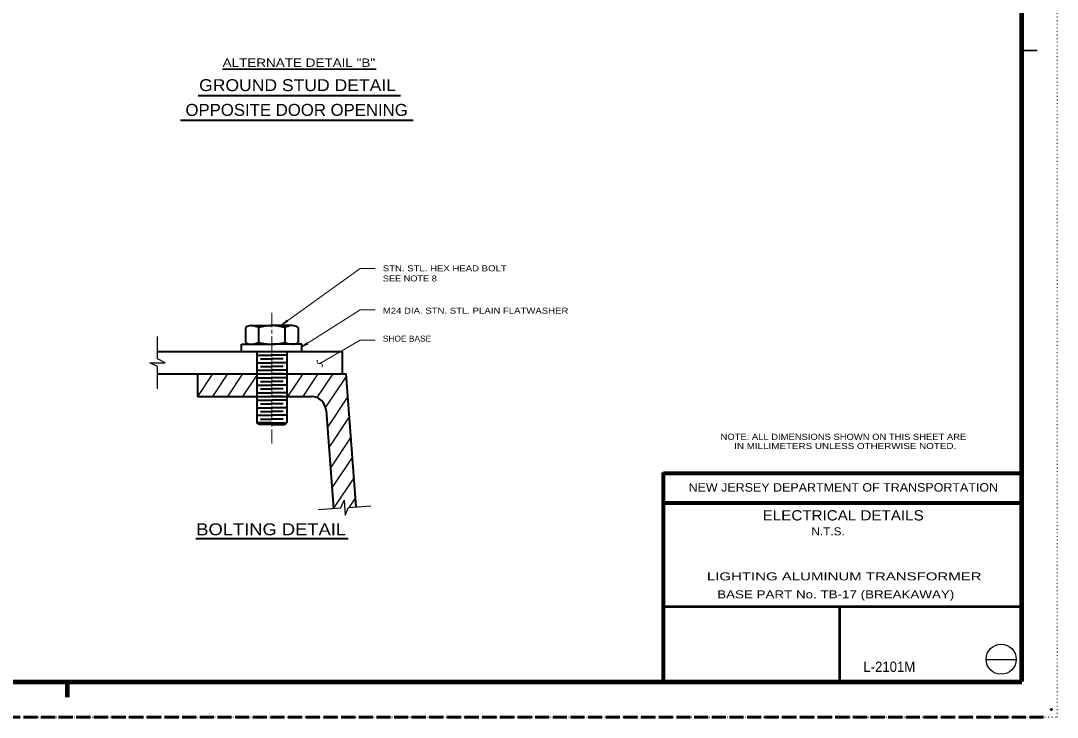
# Model space of a CAD drawing. Extents: x 312583 to 312854, y 144419 to 144597.
# Drawn here: x 312721.4 to 312853.5, y 144418.6 to 144507.4 of the extents above; entities that cross this region are included whole.
import ezdxf
from ezdxf.enums import TextEntityAlignment as Align

# ---------------------------------------------------------------- set-up
doc = ezdxf.new("R2010")
doc.units = 0
doc.header["$LTSCALE"] = 0.3
doc.header["$PDMODE"] = 32
doc.header["$PDSIZE"] = 0.15
for name, pattern in [('DOTTED', [1.5, 0.3, -1.2]), ('LONG_DASH_SHORT_DASH', [9.9, 6, -1.2, 1.5, -1.2]), ('LONG_DASHED', [7.5, 6, -1.5])]:
    doc.linetypes.add(name, pattern=pattern)
for name, color, linetype, lineweight in [('1', 7, 'Continuous', 40), ('2', 7, 'Continuous', 13), ('62', 7, 'DOTTED', 13), ('63', 7, 'LONG_DASHED', 60)]:
    doc.layers.add(name, color=color, linetype=linetype, lineweight=lineweight)

msp = doc.modelspace()

# ---------------------------------------------------------------- linework, layer by layer
at = {"layer": '1', "lineweight": 158}
for p, q in [((312849, 144423.1446), (312849, 144585.0846)), ((312616.5, 144423.0846), (312849, 144423.0846)), ((312727.35, 144421.1646), (312727.35, 144423.0846))]:
    msp.add_line(p, q, dxfattribs=at)
at = {"layer": '1', "lineweight": 35}
msp.add_line((312849, 144503.6216), (312850.932, 144503.6216), dxfattribs=at)
at = {"layer": '1', "linetype": 'LONG_DASH_SHORT_DASH', "lineweight": 13}
msp.add_line((312753.3623, 144453.4887), (312753.3623, 144470.3554), dxfattribs=at)
at = {"layer": '1'}
for p, q in [((312750.012, 144468.2931), (312750.012, 144466.3841)), ((312750.748, 144468.5384), (312753.3623, 144468.5384)), ((312751.691, 144468.2931), (312751.691, 144466.3841)), ((312755.9843, 144468.5384), (312753.3623, 144468.5384)), ((312755.0413, 144468.2931), (312755.0413, 144466.3841)), ((312756.7203, 144468.2931), (312756.7203, 144466.3841)), ((312749.529, 144465.2417), (312749.529, 144466.1464)), ((312749.529, 144466.1464), (312753.3623, 144466.1464)), ((312751.4456, 144465.2417), (312751.4456, 144456.1337)), ((312757.1956, 144466.1464), (312753.3623, 144466.1464)), ((312755.279, 144465.2417), (312755.279, 144456.1337)), ((312757.1956, 144465.2417), (312757.1956, 144466.1464)), ((312751.4456, 144464.7587), (312753.3623, 144464.7587)), ((312751.4456, 144463.8004), (312753.3623, 144463.8004)), ((312751.9286, 144464.2834), (312753.3623, 144464.2834)), ((312755.279, 144464.7587), (312753.3623, 144464.7587)), ((312754.8036, 144464.2834), (312753.3623, 144464.2834)), ((312755.279, 144463.8004), (312753.3623, 144463.8004)), ((312751.4456, 144462.8421), (312753.3623, 144462.8421)), ((312751.9286, 144463.3251), (312753.3623, 144463.3251)), ((312751.9286, 144462.3667), (312753.3623, 144462.3667)), ((312754.8036, 144463.3251), (312753.3623, 144463.3251)), ((312755.279, 144462.8421), (312753.3623, 144462.8421)), ((312754.8036, 144462.3667), (312753.3623, 144462.3667)), ((312751.4456, 144461.8837), (312753.3623, 144461.8837)), ((312751.9286, 144461.4084), (312753.3623, 144461.4084)), ((312755.279, 144461.8837), (312753.3623, 144461.8837)), ((312754.8036, 144461.4084), (312753.3623, 144461.4084)), ((312751.4456, 144460.9254), (312753.3623, 144460.9254)), ((312751.4456, 144459.9671), (312753.3623, 144459.9671)), ((312751.9286, 144460.4501), (312753.3623, 144460.4501)), ((312755.279, 144460.9254), (312753.3623, 144460.9254)), ((312754.8036, 144460.4501), (312753.3623, 144460.4501)), ((312755.279, 144459.9671), (312753.3623, 144459.9671)), ((312751.4456, 144459.0087), (312753.3623, 144459.0087)), ((312751.9286, 144459.4917), (312753.3623, 144459.4917)), ((312751.9286, 144458.5334), (312753.3623, 144458.5334)), ((312754.8036, 144459.4917), (312753.3623, 144459.4917)), ((312755.279, 144459.0087), (312753.3623, 144459.0087)), ((312754.8036, 144458.5334), (312753.3623, 144458.5334)), ((312751.4456, 144458.0504), (312753.3623, 144458.0504)), ((312751.4456, 144457.0921), (312753.3623, 144457.0921)), ((312751.9286, 144457.5751), (312753.3623, 144457.5751)), ((312755.279, 144458.0504), (312753.3623, 144458.0504)), ((312754.8036, 144457.5751), (312753.3623, 144457.5751)), ((312755.279, 144457.0921), (312753.3623, 144457.0921)), ((312753.3623, 144456.1337), (312751.4456, 144456.1337)), ((312751.7906, 144455.8961), (312751.4456, 144456.1337)), ((312753.3623, 144455.8961), (312751.7906, 144455.8961)), ((312751.9286, 144456.6167), (312753.3623, 144456.6167)), ((312754.8036, 144456.6167), (312753.3623, 144456.6167)), ((312753.3623, 144456.1337), (312755.279, 144456.1337)), ((312753.3623, 144455.8961), (312754.934, 144455.8961)), ((312754.934, 144455.8961), (312755.279, 144456.1337))]:
    msp.add_line(p, q, dxfattribs=at)
at = {"layer": '1', "lineweight": 80}
for p, q in [((312803.31, 144423.1446), (312803.31, 144449.8146)), ((312803.31, 144449.7246), (312849, 144449.7246)), ((312803.31, 144445.9146), (312849, 144445.9146))]:
    msp.add_line(p, q, dxfattribs=at)
at = {"layer": '1', "lineweight": 53}
for p, q in [((312849, 144432.6666), (312803.115, 144432.6666)), ((312825.7546, 144432.6666), (312825.7546, 144423.1446))]:
    msp.add_line(p, q, dxfattribs=at)
at = {"layer": '1', "lineweight": 25}
msp.add_line((312844.4384, 144425.966), (312848.2794, 144425.966), dxfattribs=at)
msp.add_circle((312846.3494, 144425.9805), 1.9159, dxfattribs=at)
at = {"layer": '1'}
for centre, radius, start, end in [((312750.7843, 144467.148), 1.3833, 91.66257, 124.1297), ((312750.1163, 144464.6567), 3.9611, 66.63635, 78.22986), ((312753.5376, 144461.3881), 7.1486, 91.405, 105.00202), ((312753.187, 144461.3881), 7.1486, 74.99798, 88.595), ((312756.6083, 144464.6567), 3.9611, 101.77014, 113.36365), ((312755.9403, 144467.148), 1.3833, 55.8703, 88.33743), ((312750.7843, 144467.5291), 1.3833, 235.8703, 268.33743), ((312750.1163, 144470.0204), 3.9611, 281.77014, 293.36365), ((312753.5376, 144473.2891), 7.1486, 254.99798, 268.595), ((312753.187, 144473.2891), 7.1486, 271.405, 285.00202), ((312756.6083, 144470.0204), 3.9611, 246.63635, 258.22986), ((312755.9403, 144467.5291), 1.3833, 271.66257, 304.1297)]:
    msp.add_arc(centre, radius, start, end, dxfattribs=at)
msp.add_point((312852.75, 144419.5846), dxfattribs=at)
at = {"layer": '2', "lineweight": 35}
msp.add_line((312747.078, 144501.2392), (312766.6956, 144501.2392), dxfattribs=at)
at = {"layer": '2', "lineweight": 40}
for p, q in [((312743.9953, 144497.8668), (312769.7783, 144497.8668)), ((312741.7532, 144494.7191), (312771.3897, 144494.7191)), ((312743.894, 144462.3667), (312743.894, 144459.4917)), ((312743.894, 144459.4917), (312758.384, 144459.4917)), ((312760.293, 144457.7131), (312761.2283, 144445.2011)), ((312743.7051, 144441.3688), (312763.1125, 144441.3688))]:
    msp.add_line(p, q, dxfattribs=at)
at = {"layer": '2'}
for p, q in [((312754.6503, 144468.6304), (312764.6476, 144475.7911)), ((312764.6476, 144475.7911), (312766.5643, 144475.7911)), ((312757.2186, 144465.8014), (312764.6476, 144470.5241)), ((312764.6476, 144470.5241), (312766.5643, 144470.5241)), ((312754.6503, 144468.6304), (312755.2866, 144469.2207)), ((312754.6503, 144468.6304), (312755.417, 144469.0521)), ((312755.2866, 144469.2207), (312755.1256, 144468.9754)), ((312755.417, 144469.0521), (312755.1256, 144468.9754)), ((312757.2186, 144465.8014), (312757.8933, 144466.3534)), ((312757.8933, 144466.3534), (312757.717, 144466.1157)), ((312759.488, 144463.6854), (312764.6476, 144466.6907)), ((312764.6476, 144466.6907), (312766.5643, 144466.6907)), ((312757.2186, 144465.8014), (312758.0083, 144466.1694)), ((312758.0083, 144466.1694), (312757.717, 144466.1157))]:
    msp.add_line(p, q, dxfattribs=at)
at = {"layer": '2', "lineweight": 25}
for p, q in [((312745.8106, 144462.3667), (312743.894, 144459.4917)), ((312747.7273, 144462.3667), (312745.8106, 144459.4917)), ((312749.644, 144462.3667), (312747.7273, 144459.4917)), ((312757.3106, 144462.3667), (312755.394, 144459.4917)), ((312759.2273, 144462.3667), (312757.3106, 144459.4917)), ((312761.144, 144462.3667), (312759.1276, 144459.3384)), ((312751.4456, 144462.1904), (312749.644, 144459.4917)), ((312762.8536, 144462.0524), (312760.224, 144458.1117)), ((312763.0453, 144459.4687), (312760.454, 144455.5817)), ((312763.2446, 144456.8851), (312760.6456, 144452.9981)), ((312763.4363, 144454.3014), (312760.845, 144450.4067)), ((312763.628, 144451.7101), (312761.0366, 144447.8231)), ((312763.8196, 144449.1264), (312761.2283, 144445.2394)), ((312764.0113, 144446.5427), (312763.2216, 144445.3544))]:
    msp.add_line(p, q, dxfattribs=at)
for points in [[(312738.8033, 144460.4501), (312738.8033, 144463.3174), (312737.845, 144463.8004), (312739.7616, 144463.8004), (312738.8033, 144464.2757), (312738.8033, 144467.1584)], [(312759.3193, 144445.0631), (312762.179, 144445.2701), (312762.593, 144446.2667), (312762.731, 144444.3577), (312763.1373, 144445.3467), (312766.0046, 144445.5614)]]:
    msp.add_lwpolyline(points, dxfattribs=at)
at = {"layer": '2', "lineweight": 40}
for points in [[(312738.8033, 144465.2417), (312762.3553, 144465.2417), (312762.3553, 144462.3667)], [(312738.8033, 144462.3667), (312762.8306, 144462.3667), (312764.0956, 144445.4157)]]:
    msp.add_lwpolyline(points, dxfattribs=at)
at = {"layer": '2'}
for centre, start, end in [((312759.4083, 144463.9456), 136.06269, 286.06269), ((312759.5573, 144463.4278), 316.06269, 106.06269)]:
    msp.add_arc(centre, 0.2694, start, end, dxfattribs=at)
at = {"layer": '2', "lineweight": 40}
msp.add_arc((312758.383, 144457.5712), 1.9167, 4.26806, 90, dxfattribs=at)
at = {"layer": '62'}
msp.add_lwpolyline([(312601.2, 144418.5846), (312853.5, 144418.5846), (312853.5, 144596.7846)], dxfattribs=at)
at = {"layer": '63'}
msp.add_line((312851.75, 144418.5846), (312583.526, 144418.5846), dxfattribs=at)

# ---------------------------------------------------------------- texts
at = {"layer": '1'}
for s, width, p in [('NOTE: ALL DIMENSIONS SHOWN ON THIS SHEET ARE', 1.15, (312810.5751, 144453.9543)), ('     IN MILLIMETERS UNLESS OTHERWISE NOTED.', 1.2, (312810.575, 144452.7843))]:
    msp.add_text(s, height=0.78, dxfattribs=dict(at, width=width)).set_placement(p)
for s, height, width, p in [('NEW JERSEY DEPARTMENT OF TRANSPORTATION', 1.08, 1.1, (312826.2285, 144447.3546)), ('ELECTRICAL DETAILS', 1.315, 1.1, (312826.2107, 144443.6759)), ('L-2101M', 1.319, 0.95, (312832.0897, 144424.3636))]:
    msp.add_text(s, height=height, dxfattribs=dict(at, width=width)).set_placement(p, align=Align.CENTER)
at = {"layer": '2'}
for s, height, width, p in [('ALTERNATE DETAIL "B"', 1.07, 1.2, (312756.8277, 144501.5177)), ('GROUND STUD DETAIL', 1.52, 1.1, (312756.6539, 144498.4272)), ('OPPOSITE DOOR OPENING', 1.52, 1.05, (312756.5368, 144495.2716)), ('BOLTING DETAIL', 1.52, 1.15, (312753.2918, 144441.7924)), ('    N.T.S.  ', 1.02, 1.1, (312823.87, 144441.778)), ('        LIGHTING ALUMINUM TRANSFORMER       ', 1.02, 1.4, (312826.0766, 144436.0399)), ('       BASE PART No. TB-17 (BREAKAWAY)      ', 1.02, 1.25, (312825.0225, 144433.7476))]:
    msp.add_text(s, height=height, dxfattribs=dict(at, width=width)).set_placement(p, align=Align.CENTER)
for s, width, p in [('STN. STL. HEX HEAD BOLT', 1.2, (312767.5226, 144475.4521)), ('SEE NOTE 8', 1.15, (312767.5226, 144474.1587)), ('M24 DIA. STN. STL. PLAIN FLATWASHER', 1.2, (312767.5226, 144470.0448)), ('SHOE BASE', 1.05, (312767.5226, 144466.492))]:
    msp.add_text(s, height=0.76, dxfattribs=dict(at, width=width)).set_placement(p)

doc.saveas('drawing.dxf')
